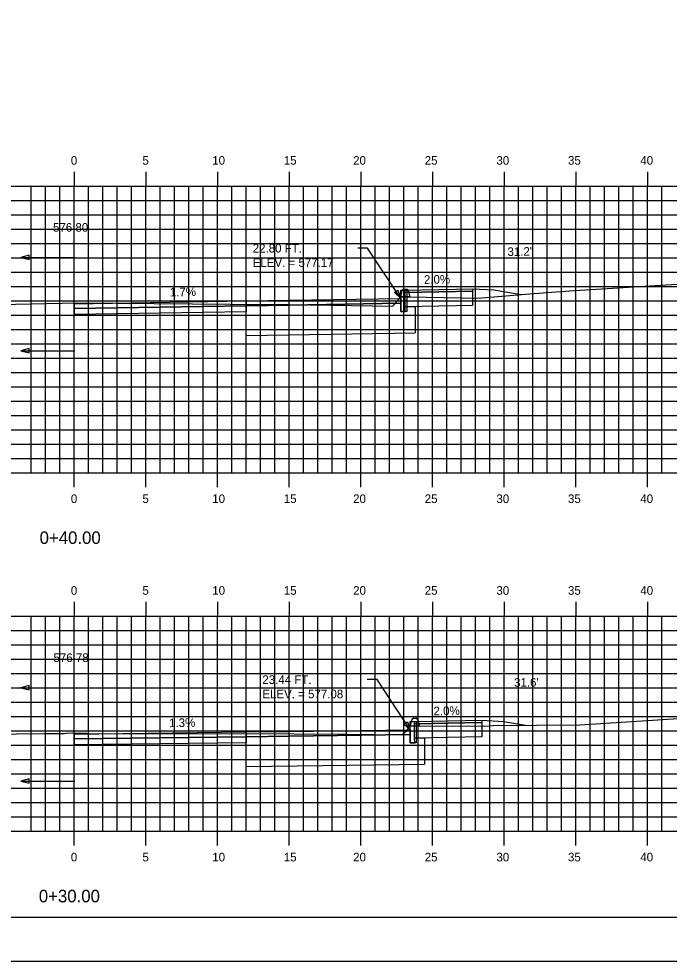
# Model space of a CAD drawing. Extents: x 1048121 to 1048291, y 781387 to 781497.
# Drawn here: x 1048200.5 to 1048245.9, y 781387.3 to 781453 of the extents above; entities that cross this region are included whole.
import ezdxf

# ---------------------------------------------------------------- set-up
doc = ezdxf.new("R2010")
doc.units = 0
for name, color, linetype in [('ANNOTATION', 7, 'Continuous'), ('BORDER', 7, 'Continuous'), ('D_Curb_Type1_Lt', 7, 'Continuous'), ('D_Roadway_Berm', 7, 'Continuous'), ('D_Roadway_Centerline', 7, 'Continuous'), ('D_Roadway_Centerline_Text', 7, 'Continuous'), ('D_Roadway_Edge_Shoulder', 7, 'Continuous'), ('D_Roadway_Edge_TW', 7, 'Continuous'), ('D_Roadway_Pavement', 7, 'Continuous'), ('D_Roadway_Sidewalks_Paved', 7, 'Continuous'), ('D_Roadway_SlopeLines', 7, 'Continuous'), ('D_Roadway_SubGrade', 7, 'Continuous'), ('D_Text_Standard', 7, 'Continuous'), ('H_V ANNOTATION', 7, 'Continuous'), ('MAJOR', 7, 'Continuous'), ('MINOR', 7, 'Continuous'), ('PLOT BOUNDARY', 7, 'Continuous'), ('S_Curb_Type_3', 7, 'Continuous'), ('S_Roadway_Centerline', 7, 'Continuous')]:
    doc.layers.add(name, color=color, linetype=linetype)

msp = doc.modelspace()

# ---------------------------------------------------------------- linework, layer by layer
at = {"layer": 'ANNOTATION'}
for p, q in [((1048200.626, 781436.411), (1048204.401, 781436.411)), ((1048200.626, 781429.893), (1048204.401, 781429.893)), ((1048200.626, 781406.391), (1048204.401, 781406.391)), ((1048200.626, 781399.873), (1048204.401, 781399.873))]:
    msp.add_line(p, q, dxfattribs=at)
for points in [[(1048201.226, 781436.561), (1048200.626, 781436.411), (1048201.226, 781436.261)], [(1048201.226, 781430.043), (1048200.626, 781429.893), (1048201.226, 781429.743)], [(1048201.226, 781406.541), (1048200.626, 781406.391), (1048201.226, 781406.241)], [(1048201.226, 781400.023), (1048200.626, 781399.873), (1048201.226, 781399.723)]]:
    msp.add_lwpolyline(points, close=True, dxfattribs=at)
at = {"layer": 'BORDER'}
msp.add_lwpolyline([(1048129.363, 781390.375), (1048289.363, 781390.375), (1048289.363, 781495.375), (1048129.363, 781495.375)], close=True, dxfattribs=at)
at = {"layer": 'D_Curb_Type1_Lt'}
for points in [[(1048227.552, 781434.132), (1048227.552, 781432.632), (1048227.135, 781432.632), (1048227.135, 781434.132)], [(1048228.221, 781404.037), (1048228.221, 781402.537), (1048227.805, 781402.537), (1048227.805, 781404.037)]]:
    msp.add_lwpolyline(points, close=True, dxfattribs=at)
at = {"layer": 'D_Roadway_Berm'}
for points in [[(1048232.135, 781434.226), (1048233.635, 781434.136)], [(1048232.805, 781404.131), (1048234.305, 781404.041)]]:
    msp.add_lwpolyline(points, dxfattribs=at)
at = {"layer": 'D_Roadway_Centerline'}
for p, q in [((1048204.363, 781429.893), (1048204.363, 781436.45)), ((1048204.363, 781433.171), (1048204.363, 781432.421)), ((1048204.363, 781399.873), (1048204.363, 781406.43)), ((1048204.363, 781403.151), (1048204.363, 781402.401))]:
    msp.add_line(p, q, dxfattribs=at)
at = {"layer": 'D_Roadway_Edge_Shoulder'}
for points in [[(1048216.363, 781433.37), (1048219.363, 781433.42), (1048227.134, 781433.549), (1048227.134, 781433.215), (1048219.363, 781433.087), (1048216.363, 781433.037)], [(1048216.363, 781403.306), (1048219.363, 781403.345), (1048227.804, 781403.454), (1048227.804, 781403.121), (1048219.363, 781403.012), (1048216.363, 781402.973)]]:
    msp.add_lwpolyline(points, close=True, dxfattribs=at)
at = {"layer": 'D_Roadway_Edge_TW'}
for points in [[(1048204.363, 781433.171), (1048216.363, 781433.37), (1048216.363, 781433.037), (1048204.363, 781432.838)], [(1048204.363, 781403.151), (1048216.363, 781403.306), (1048216.363, 781402.973), (1048204.363, 781402.818)]]:
    msp.add_lwpolyline(points, dxfattribs=at)
at = {"layer": 'D_Roadway_Pavement'}
for points in [[(1048204.363, 781432.838), (1048216.363, 781433.037), (1048216.363, 781432.62), (1048204.363, 781432.421)], [(1048204.363, 781402.818), (1048216.363, 781402.973), (1048216.363, 781402.556), (1048204.363, 781402.401)]]:
    msp.add_lwpolyline(points, dxfattribs=at)
at = {"layer": 'D_Roadway_Sidewalks_Paved'}
for points in [[(1048227.435, 781434.132), (1048232.135, 781434.226), (1048232.135, 781434.059), (1048227.435, 781433.965)], [(1048228.105, 781404.037), (1048232.805, 781404.131), (1048232.805, 781403.965), (1048228.105, 781403.871)]]:
    msp.add_lwpolyline(points, close=True, dxfattribs=at)
at = {"layer": 'D_Roadway_SlopeLines'}
for points in [[(1048233.635, 781434.136), (1048235.548, 781433.817)], [(1048234.305, 781404.041), (1048235.974, 781403.763)]]:
    msp.add_lwpolyline(points, dxfattribs=at)
at = {"layer": 'D_Roadway_SubGrade'}
for p, q in [((1048216.363, 781430.954), (1048228.134, 781431.149)), ((1048216.363, 781400.89), (1048228.804, 781401.05))]:
    msp.add_line(p, q, dxfattribs=at)
for points in [[(1048227.435, 781433.965), (1048232.135, 781434.059), (1048232.135, 781433.059), (1048227.435, 781432.965)], [(1048228.105, 781403.871), (1048232.805, 781403.965), (1048232.805, 781402.965), (1048228.105, 781402.871)]]:
    msp.add_lwpolyline(points, close=True, dxfattribs=at)
for points in [[(1048216.363, 781430.954), (1048216.363, 781433.037), (1048216.363, 781433.037), (1048219.363, 781433.087), (1048227.134, 781433.215), (1048227.134, 781432.632), (1048227.444, 781432.632), (1048227.435, 781432.965), (1048228.134, 781432.979), (1048228.134, 781431.149)], [(1048216.363, 781400.89), (1048216.363, 781402.973), (1048216.363, 781402.973), (1048219.363, 781403.012), (1048227.804, 781403.121), (1048227.804, 781402.537), (1048228.114, 781402.537), (1048228.105, 781402.871), (1048228.804, 781402.885), (1048228.804, 781401.05)]]:
    msp.add_lwpolyline(points, dxfattribs=at)
at = {"layer": 'D_Text_Standard'}
for points in [[(1048227.134, 781433.549), (1048224.817, 781437.049), (1048224.137, 781437.049)], [(1048227.804, 781403.454), (1048225.486, 781406.954), (1048224.806, 781406.954)]]:
    msp.add_lwpolyline(points, dxfattribs=at)
for points in [[(1048227.134, 781433.549), (1048226.692, 781433.954), (1048226.934, 781434.114)], [(1048227.804, 781403.454), (1048227.361, 781403.859), (1048227.604, 781404.02)]]:
    msp.add_lwpolyline(points, close=True, dxfattribs=at)
at = {"layer": 'MAJOR'}
for p, q in [((1048204.363, 781442.377), (1048204.363, 781441.375)), ((1048209.363, 781442.377), (1048209.363, 781441.375)), ((1048214.363, 781442.377), (1048214.363, 781441.375)), ((1048219.363, 781442.377), (1048219.363, 781441.375)), ((1048224.363, 781442.377), (1048224.363, 781441.375)), ((1048229.363, 781442.377), (1048229.363, 781441.375)), ((1048234.363, 781442.377), (1048234.363, 781441.375)), ((1048239.363, 781442.377), (1048239.363, 781441.375)), ((1048244.363, 781442.377), (1048244.363, 781441.375)), ((1048134.363, 781441.375), (1048274.363, 781441.375)), ((1048134.363, 781441.375), (1048274.363, 781441.375)), ((1048204.363, 781421.375), (1048204.363, 781441.375)), ((1048209.363, 781421.375), (1048209.363, 781441.375)), ((1048214.363, 781421.375), (1048214.363, 781441.375)), ((1048219.363, 781421.375), (1048219.363, 781441.375)), ((1048224.363, 781421.375), (1048224.363, 781441.375)), ((1048229.363, 781421.375), (1048229.363, 781441.375)), ((1048234.363, 781421.375), (1048234.363, 781441.375)), ((1048239.363, 781421.375), (1048239.363, 781441.375)), ((1048244.363, 781421.375), (1048244.363, 781441.375)), ((1048134.363, 781436.375), (1048274.363, 781436.375)), ((1048134.363, 781431.375), (1048274.363, 781431.375)), ((1048134.363, 781426.375), (1048274.363, 781426.375)), ((1048134.363, 781421.375), (1048274.363, 781421.375)), ((1048134.363, 781421.375), (1048274.363, 781421.375)), ((1048204.363, 781420.373), (1048204.363, 781421.375)), ((1048209.363, 781420.373), (1048209.363, 781421.375)), ((1048214.363, 781420.373), (1048214.363, 781421.375)), ((1048219.363, 781420.373), (1048219.363, 781421.375)), ((1048224.363, 781420.373), (1048224.363, 781421.375)), ((1048229.363, 781420.373), (1048229.363, 781421.375)), ((1048234.363, 781420.373), (1048234.363, 781421.375)), ((1048239.363, 781420.373), (1048239.363, 781421.375)), ((1048244.363, 781420.373), (1048244.363, 781421.375)), ((1048204.363, 781412.377), (1048204.363, 781411.375)), ((1048209.363, 781412.377), (1048209.363, 781411.375)), ((1048214.363, 781412.377), (1048214.363, 781411.375)), ((1048219.363, 781412.377), (1048219.363, 781411.375)), ((1048224.363, 781412.377), (1048224.363, 781411.375)), ((1048229.363, 781412.377), (1048229.363, 781411.375)), ((1048234.363, 781412.377), (1048234.363, 781411.375)), ((1048239.363, 781412.377), (1048239.363, 781411.375)), ((1048244.363, 781412.377), (1048244.363, 781411.375)), ((1048134.363, 781411.375), (1048274.363, 781411.375)), ((1048134.363, 781411.375), (1048274.363, 781411.375)), ((1048204.363, 781396.375), (1048204.363, 781411.375)), ((1048209.363, 781396.375), (1048209.363, 781411.375)), ((1048214.363, 781396.375), (1048214.363, 781411.375)), ((1048219.363, 781396.375), (1048219.363, 781411.375)), ((1048224.363, 781396.375), (1048224.363, 781411.375)), ((1048229.363, 781396.375), (1048229.363, 781411.375)), ((1048234.363, 781396.375), (1048234.363, 781411.375)), ((1048239.363, 781396.375), (1048239.363, 781411.375)), ((1048244.363, 781396.375), (1048244.363, 781411.375)), ((1048134.363, 781406.375), (1048274.363, 781406.375)), ((1048134.363, 781401.375), (1048274.363, 781401.375)), ((1048134.363, 781396.375), (1048274.363, 781396.375)), ((1048134.363, 781396.375), (1048274.363, 781396.375)), ((1048204.363, 781395.373), (1048204.363, 781396.375)), ((1048209.363, 781395.373), (1048209.363, 781396.375)), ((1048214.363, 781395.373), (1048214.363, 781396.375)), ((1048219.363, 781395.373), (1048219.363, 781396.375)), ((1048224.363, 781395.373), (1048224.363, 781396.375)), ((1048229.363, 781395.373), (1048229.363, 781396.375)), ((1048234.363, 781395.373), (1048234.363, 781396.375)), ((1048239.363, 781395.373), (1048239.363, 781396.375)), ((1048244.363, 781395.373), (1048244.363, 781396.375))]:
    msp.add_line(p, q, dxfattribs=at)
at = {"layer": 'MINOR'}
for p, q in [((1048201.363, 781421.375), (1048201.363, 781441.375)), ((1048202.363, 781421.375), (1048202.363, 781441.375)), ((1048203.363, 781421.375), (1048203.363, 781441.375)), ((1048205.363, 781421.375), (1048205.363, 781441.375)), ((1048206.363, 781421.375), (1048206.363, 781441.375)), ((1048207.363, 781421.375), (1048207.363, 781441.375)), ((1048208.363, 781421.375), (1048208.363, 781441.375)), ((1048210.363, 781421.375), (1048210.363, 781441.375)), ((1048211.363, 781421.375), (1048211.363, 781441.375)), ((1048212.363, 781421.375), (1048212.363, 781441.375)), ((1048213.363, 781421.375), (1048213.363, 781441.375)), ((1048215.363, 781421.375), (1048215.363, 781441.375)), ((1048216.363, 781421.375), (1048216.363, 781441.375)), ((1048217.363, 781421.375), (1048217.363, 781441.375)), ((1048218.363, 781421.375), (1048218.363, 781441.375)), ((1048220.363, 781421.375), (1048220.363, 781441.375)), ((1048221.363, 781421.375), (1048221.363, 781441.375)), ((1048222.363, 781421.375), (1048222.363, 781441.375)), ((1048223.363, 781421.375), (1048223.363, 781441.375)), ((1048225.363, 781421.375), (1048225.363, 781441.375)), ((1048226.363, 781421.375), (1048226.363, 781441.375)), ((1048227.363, 781421.375), (1048227.363, 781441.375)), ((1048228.363, 781421.375), (1048228.363, 781441.375)), ((1048230.363, 781421.375), (1048230.363, 781441.375)), ((1048231.363, 781421.375), (1048231.363, 781441.375)), ((1048232.363, 781421.375), (1048232.363, 781441.375)), ((1048233.363, 781421.375), (1048233.363, 781441.375)), ((1048235.363, 781421.375), (1048235.363, 781441.375)), ((1048236.363, 781421.375), (1048236.363, 781441.375)), ((1048237.363, 781421.375), (1048237.363, 781441.375)), ((1048238.363, 781421.375), (1048238.363, 781441.375)), ((1048240.363, 781421.375), (1048240.363, 781441.375)), ((1048241.363, 781421.375), (1048241.363, 781441.375)), ((1048242.363, 781421.375), (1048242.363, 781441.375)), ((1048243.363, 781421.375), (1048243.363, 781441.375)), ((1048245.363, 781421.375), (1048245.363, 781441.375)), ((1048134.363, 781440.375), (1048274.363, 781440.375)), ((1048134.363, 781439.375), (1048274.363, 781439.375)), ((1048134.363, 781438.375), (1048274.363, 781438.375)), ((1048134.363, 781437.375), (1048274.363, 781437.375)), ((1048134.363, 781435.375), (1048274.363, 781435.375)), ((1048134.363, 781434.375), (1048274.363, 781434.375)), ((1048134.363, 781433.375), (1048274.363, 781433.375)), ((1048134.363, 781432.375), (1048274.363, 781432.375)), ((1048134.363, 781430.375), (1048274.363, 781430.375)), ((1048134.363, 781429.375), (1048274.363, 781429.375)), ((1048134.363, 781428.375), (1048274.363, 781428.375)), ((1048134.363, 781427.375), (1048274.363, 781427.375)), ((1048134.363, 781425.375), (1048274.363, 781425.375)), ((1048134.363, 781424.375), (1048274.363, 781424.375)), ((1048134.363, 781423.375), (1048274.363, 781423.375)), ((1048134.363, 781422.375), (1048274.363, 781422.375)), ((1048201.363, 781396.375), (1048201.363, 781411.375)), ((1048202.363, 781396.375), (1048202.363, 781411.375)), ((1048203.363, 781396.375), (1048203.363, 781411.375)), ((1048205.363, 781396.375), (1048205.363, 781411.375)), ((1048206.363, 781396.375), (1048206.363, 781411.375)), ((1048207.363, 781396.375), (1048207.363, 781411.375)), ((1048208.363, 781396.375), (1048208.363, 781411.375)), ((1048210.363, 781396.375), (1048210.363, 781411.375)), ((1048211.363, 781396.375), (1048211.363, 781411.375)), ((1048212.363, 781396.375), (1048212.363, 781411.375)), ((1048213.363, 781396.375), (1048213.363, 781411.375)), ((1048215.363, 781396.375), (1048215.363, 781411.375)), ((1048216.363, 781396.375), (1048216.363, 781411.375)), ((1048217.363, 781396.375), (1048217.363, 781411.375)), ((1048218.363, 781396.375), (1048218.363, 781411.375)), ((1048220.363, 781396.375), (1048220.363, 781411.375)), ((1048221.363, 781396.375), (1048221.363, 781411.375)), ((1048222.363, 781396.375), (1048222.363, 781411.375)), ((1048223.363, 781396.375), (1048223.363, 781411.375)), ((1048225.363, 781396.375), (1048225.363, 781411.375)), ((1048226.363, 781396.375), (1048226.363, 781411.375)), ((1048227.363, 781396.375), (1048227.363, 781411.375)), ((1048228.363, 781396.375), (1048228.363, 781411.375)), ((1048230.363, 781396.375), (1048230.363, 781411.375)), ((1048231.363, 781396.375), (1048231.363, 781411.375)), ((1048232.363, 781396.375), (1048232.363, 781411.375)), ((1048233.363, 781396.375), (1048233.363, 781411.375)), ((1048235.363, 781396.375), (1048235.363, 781411.375)), ((1048236.363, 781396.375), (1048236.363, 781411.375)), ((1048237.363, 781396.375), (1048237.363, 781411.375)), ((1048238.363, 781396.375), (1048238.363, 781411.375)), ((1048240.363, 781396.375), (1048240.363, 781411.375)), ((1048241.363, 781396.375), (1048241.363, 781411.375)), ((1048242.363, 781396.375), (1048242.363, 781411.375)), ((1048243.363, 781396.375), (1048243.363, 781411.375)), ((1048245.363, 781396.375), (1048245.363, 781411.375)), ((1048134.363, 781410.375), (1048274.363, 781410.375)), ((1048134.363, 781409.375), (1048274.363, 781409.375)), ((1048134.363, 781408.375), (1048274.363, 781408.375)), ((1048134.363, 781407.375), (1048274.363, 781407.375)), ((1048134.363, 781405.375), (1048274.363, 781405.375)), ((1048134.363, 781404.375), (1048274.363, 781404.375)), ((1048134.363, 781403.375), (1048274.363, 781403.375)), ((1048134.363, 781402.375), (1048274.363, 781402.375)), ((1048134.363, 781400.375), (1048274.363, 781400.375)), ((1048134.363, 781399.375), (1048274.363, 781399.375)), ((1048134.363, 781398.375), (1048274.363, 781398.375)), ((1048134.363, 781397.375), (1048274.363, 781397.375))]:
    msp.add_line(p, q, dxfattribs=at)
at = {"layer": 'PLOT BOUNDARY'}
msp.add_lwpolyline([(1048121.27, 781387.316), (1048291.27, 781387.316), (1048291.27, 781497.316), (1048121.27, 781497.316)], close=True, dxfattribs=at)
at = {"layer": 'S_Curb_Type_3'}
for points in [[(1048227.657, 781434.102), (1048227.76, 781433.658), (1048227.135, 781433.658), (1048227.238, 781434.102)], [(1048227.36, 781434.199), (1048227.536, 781434.199)], [(1048228.334, 781404.158), (1048228.436, 781403.713), (1048227.811, 781403.713), (1048227.914, 781404.158)], [(1048228.036, 781404.255), (1048228.212, 781404.255)]]:
    msp.add_lwpolyline(points, dxfattribs=at)
for centre, start, end in [((1048227.36, 781434.074), 90, 167.00538), ((1048227.536, 781434.074), 12.99462, 90), ((1048228.036, 781404.13), 90, 167.00538), ((1048228.212, 781404.13), 12.99462, 90)]:
    msp.add_arc(centre, 0.125, start, end, dxfattribs=at)
at = {"layer": 'S_Roadway_Centerline'}
for points in [[(1048198.044, 781433.091), (1048204.599, 781433.233), (1048217.945, 781433.128), (1048217.946, 781433.126), (1048219.055, 781433.123), (1048219.361, 781433.122), (1048226.589, 781433.018), (1048226.635, 781433.06), (1048227.135, 781433.658), (1048227.707, 781433.659), (1048232.526, 781433.563), (1048234.199, 781433.699), (1048235.848, 781433.844), (1048238.921, 781434.065), (1048251.629, 781434.86), (1048256.981, 781435.098), (1048257.889, 781435.134), (1048260.889, 781435.172), (1048273.362, 781435.327), (1048274.363, 781435.397)], [(1048198.387, 781403.15), (1048202.265, 781403.193), (1048203.654, 781403.201), (1048203.786, 781403.224), (1048204.236, 781403.233), (1048205.229, 781403.226), (1048205.238, 781403.202), (1048219.707, 781403.164), (1048223.407, 781403.154), (1048227.216, 781403.098), (1048227.545, 781403.394), (1048227.811, 781403.713), (1048231.833, 781403.722), (1048233.007, 781403.698), (1048233.59, 781403.745), (1048239.62, 781403.79), (1048250.848, 781404.533)]]:
    msp.add_lwpolyline(points, dxfattribs=at)

# ---------------------------------------------------------------- texts
at = {"layer": 'ANNOTATION'}
for s, rotation, p in [("31.2'", 0.7396, (1048234.586, 781436.505)), ('2.0%', 1.14576, (1048228.761, 781434.559)), ('1.7%', 0.94948, (1048211.028, 781433.682)), ("31.6'", 0.7396, (1048235.045, 781406.451)), ('2.0%', 1.14576, (1048229.43, 781404.464)), ('1.3%', 0.7396, (1048210.978, 781403.637))]:
    msp.add_text(s, height=0.6, rotation=rotation, dxfattribs=at).set_placement(p)
at = {"layer": 'D_Roadway_Centerline'}
for s, p in [('C', (1048204.358, 781433.171)), ('L', (1048204.363, 781433.164)), ('C', (1048204.358, 781403.151)), ('L', (1048204.363, 781403.144))]:
    msp.add_text(s, height=0.0146, dxfattribs=at).set_placement(p)
at = {"layer": 'D_Roadway_Centerline_Text'}
for s, p in [('576.80', (1048202.88, 781438.203)), ('576.78', (1048202.91, 781408.183))]:
    msp.add_text(s, height=0.6, dxfattribs=at).set_placement(p)
at = {"layer": 'D_Text_Standard'}
for s, p in [('22.80 FT.', (1048216.812, 781436.749)), ('ELEV. = 577.17', (1048216.812, 781435.749)), ('23.44 FT.', (1048217.481, 781406.654)), ('ELEV. = 577.08', (1048217.481, 781405.654))]:
    msp.add_text(s, height=0.6, dxfattribs=at).set_placement(p)
at = {"layer": 'H_V ANNOTATION'}
for s, height, p in [('0', 0.6, (1048204.122, 781442.875)), ('5', 0.6, (1048209.114, 781442.875)), ('10', 0.6, (1048213.988, 781442.875)), ('15', 0.6, (1048218.98, 781442.875)), ('20', 0.6, (1048223.817, 781442.875)), ('25', 0.6, (1048228.809, 781442.875)), ('30', 0.6, (1048233.812, 781442.875)), ('35', 0.6, (1048238.804, 781442.875)), ('40', 0.6, (1048243.849, 781442.875)), ('0', 0.6, (1048204.122, 781419.275)), ('5', 0.6, (1048209.114, 781419.275)), ('10', 0.6, (1048213.988, 781419.275)), ('15', 0.6, (1048218.98, 781419.275)), ('20', 0.6, (1048223.817, 781419.275)), ('25', 0.6, (1048228.809, 781419.275)), ('30', 0.6, (1048233.812, 781419.275)), ('35', 0.6, (1048238.804, 781419.275)), ('40', 0.6, (1048243.849, 781419.275)), ('0+40.00', 0.875, (1048201.944, 781416.419)), ('0', 0.6, (1048204.122, 781412.875)), ('5', 0.6, (1048209.114, 781412.875)), ('10', 0.6, (1048213.988, 781412.875)), ('15', 0.6, (1048218.98, 781412.875)), ('20', 0.6, (1048223.817, 781412.875)), ('25', 0.6, (1048228.809, 781412.875)), ('30', 0.6, (1048233.812, 781412.875)), ('35', 0.6, (1048238.804, 781412.875)), ('40', 0.6, (1048243.849, 781412.875)), ('0', 0.6, (1048204.122, 781394.275)), ('5', 0.6, (1048209.114, 781394.275)), ('10', 0.6, (1048213.988, 781394.275)), ('15', 0.6, (1048218.98, 781394.275)), ('20', 0.6, (1048223.817, 781394.275)), ('25', 0.6, (1048228.809, 781394.275)), ('30', 0.6, (1048233.812, 781394.275)), ('35', 0.6, (1048238.804, 781394.275)), ('40', 0.6, (1048243.849, 781394.275)), ('0+30.00', 0.875, (1048201.889, 781391.419))]:
    msp.add_text(s, height=height, dxfattribs=at).set_placement(p)
at = {"layer": 'S_Roadway_Centerline'}
for s, p in [('C', (1048204.594, 781433.233)), ('L', (1048204.599, 781433.226)), ('L', (1048204.228, 781403.226)), ('C', (1048204.231, 781403.233))]:
    msp.add_text(s, height=0.0146, dxfattribs=at).set_placement(p)

doc.saveas('drawing.dxf')
